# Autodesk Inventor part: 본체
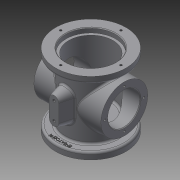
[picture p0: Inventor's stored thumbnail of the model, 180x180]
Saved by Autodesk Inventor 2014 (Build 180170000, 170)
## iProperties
Created: 2018-02
Part Number: 본체
Material: Generic
Document SubType Name: Modeling
Designer: kb542
Density: 1 g/cm^3
Appearance: Default
Author: kb542
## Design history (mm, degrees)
sketch "스케치1"
  geometry: L1 (0, 0)-(0, 108); L2 (-33, 0)-(-52.5, 0); L3 (-52.5, 0)-(-52.5, 10); L4 (-52.5, 10)-(-38, 10); L5 (-38, 10)-(-38, 98); L6 (-38, 98)-(-52.5, 98); L7 (-52.5, 98)-(-52.5, 108); L8 (-52.5, 108)-(-33, 108); L9 (-33, 108)-(-33, 0)
  constraints: 18 end point, 4 parallel, 4 perpendicular, 2 horizontal alignment, 1 vertical
  dimensions: "d0" = 105 diameter of L3 L1; "d1" = 66 diameter of L9 L1; "d2" = 76 diameter of L5 L1; "d3" = 105 diameter of L7 L1; "d4" = 10 distance between parallel lines of L2 L4; "d5" = 10 distance between parallel lines of L6 L8; "d6" = 108 distance between parallel lines of L2 L8
revolve "회전1" sketch "스케치1" stored, may be unused: angle "d7" = 90 deg
node "작업 평면2"
  node "작업 평면1"
sketch "스케치3"
  geometry: L1 (-38, -44)-(-38, 44) reference; L2 (52.5, 44)-(-52.5, 44) reference; C1 r 35 at (0, 0); 3 further points
  constraints: 2 midpoint, 1 centre point, 1 horizontal alignment, 1 vertical alignment
  dimensions: "d10" = 70 diameter of C1
extrude "돌출1" join sketch "스케치3" stored distance "d11" = 10; taper "d12" = 0 deg
sketch "스케치4"
  geometry: C1 r 35 at (0, 0) reference; C2 r 24 at (0, 0); 1 further point
  constraints: 1 centre point, 1 coincident
  dimensions: "d13" = 48 diameter of C2
extrude "돌출2" cut sketch "스케치4" stored distance "d14" = 10; taper "d15" = 0 deg
sketch "스케치5"
  geometry: L1 (108, 33)-(0, 33) reference; L2 (108, -33)-(0, -33) reference; L3 (30, 50)-(30, 33) reference; L4 (30, -33)-(30, -50) reference; L5 (30, 33)-(30, 0); L6 (30, 0)-(0, 0); L7 (0, 0)-(0, 33)
  constraints: 6 end point, 2 perpendicular, 1 collinear, 1 vertical
revolve "회전2" sketch "스케치5" stored, may be unused: angle "d17" = 90 deg
sketch "스케치6"
  geometry: L1 (0, -52.5)-(0, 52.5) reference; L2 (30, 33)-(30, -33) reference; L3 (30, 50)-(30, 33) reference; L4 (30, 33)-(22, 33); L5 (22, 33)-(22, 5); L6 (22, 5)-(16, 5); L7 (16, 5)-(16, 34); L8 (16, 34)-(0, 34); L9 (0, 0)-(30, 0); L10 (108, -33)-(108, 33) reference
  constraints: 12 end point, 3 perpendicular, 2 parallel, 1 midpoint, 1 point on line
  dimensions: "d18" = 16 distance between parallel lines of L1 L7; "d19" = 5 distance between parallel lines of L9 L6; "d20" = 86 distance between parallel lines of L5 L10; "d21" = 68 diameter of L8 L9
revolve "회전3" sketch "스케치6" stored, may be unused: angle "d22" = 90 deg
sketch "스케치7"
  geometry: L1 (108, 33)-(22, 33) reference; L2 (108, -33)-(22, -33) reference; L3 (108, -33)-(108, 33) reference; L4 (108, 0)-(101, 0); L5 (101, 0)-(101, 33); 1 further point
  constraints: 4 end point, 2 perpendicular, 1 midpoint, 1 point on line
  dimensions: "d23" = 7 distance of L4.start L4.end
revolve "회전4" sketch "스케치7" stored, may be unused: angle "d24" = 90 deg
sketch "스케치8"
  geometry: L1 (108, -52.5)-(108, 52.5) reference; L2 (101, -33)-(101, 33) reference; L3 (101, 0)-(108, 0); L4 (101, 37)-(108, 37); L5 (101, 33)-(101, 37); 1 further point
  constraints: 6 end point, 2 midpoint, 2 perpendicular, 2 point on line
  dimensions: "d25" = 74 diameter of L4 L3
revolve "회전5" sketch "스케치8" stored, may be unused: angle "d26" = 90 deg
sketch "스케치9" dims "d27" = 90
  geometry: C1 r 37 at (0, 0) reference; C2 r 52.5 at (0, 0) reference; 2 further points
  constraints: 2 vertical alignment, 1 coincident, 2 other
hole "구멍1" sketch "스케치9" at (0, 45) diameter "d28" = 3.242; stored, may be unused: countersink angle "d32" = 90 deg, drill point angle "d34" = 118 deg; dims "d29" = 4, "d30" = 4, "d31" = 2, "d33" = 6
node "작업 평면3"
sketch "스케치10" dims "d38" = 58
  geometry: C1 r 24 at (0, 0) reference; C2 r 35 at (0, 0) reference; 3 further points
  constraints: 2 vertical alignment, 1 coincident, 2 other
hole "구멍2" sketch "스케치10" at (0, 29) diameter "d39" = 3.242; stored, may be unused: countersink angle "d43" = 90 deg, drill point angle "d45" = 118 deg; dims "d40" = 4, "d41" = 4, "d42" = 2, "d44" = 6
node "작업 평면4"
sketch "스케치12"
  geometry: L1 (67, 0)-(41, 0); L2 (67, 7)-(41, 7); L3 (41, -7)-(67, -7); L4 (19, -50)-(89, -50) reference; A1 r 7 centre (67, 0) between (67, -7) and (67, 7); A2 r 7 centre (41, 0) between (41, 7) and (41, -7); 3 further points
  constraints: 8 end point, 4 point on circle, 4 tangent, 2 centre point, 2 midpoint, 1 horizontal, 1 horizontal alignment, 1 parallel, 1 vertical alignment
  dimensions: "d50" = 7 radius of A1; "d51" = 40 dimension on A2 A1
extrude "돌출3" join sketch "스케치12" stored distance "d52" = 10; taper "d53" = 15 deg
sketch "스케치15"
  geometry: A1 r 7 centre (0, 41) between (-7, 41) and (7, 41) reference; A2 r 7 centre (0, 67) between (7, 67) and (-7, 67) reference; 3 further points
  constraints: 2 coincident
hole "구멍3" sketch "스케치15" at (0, 67), (0, 41) diameter "d54" = 4.134; stored, may be unused: countersink angle "d58" = 90 deg, drill point angle "d60" = 118 deg; dims "d55" = 6, "d56" = 4, "d57" = 2, "d59" = 8
sketch "스케치16"
  geometry: L1 (0, 0)-(43, 0); C1 r 38 at (0, 0) reference; 1 further point
  constraints: 2 end point, 1 coincident, 1 horizontal, 1 other
  dimensions: "d61" = 43 distance of L1.start L1.end
extrude "돌출4" join sketch "스케치16" distance "d62" = 0.5; taper "d63" = 0 deg
chamfer "모따기1" distance "d64" = 1; stored, may be unused: second distance "d65" = 2, angle "d66" = 45 deg
fillet "모깎기1" dims "d67" = 3
fillet "모깎기2" dims "d68" = 3
chamfer "모따기2" distance "d69" = 1; stored, may be unused: second distance "d70" = 2, angle "d71" = 45 deg
fillet "모깎기3" dims "d72" = 3
node "솔리드1"
mirror "대칭1"
pattern_circular "원형 패턴1" dims angle "d36" = 360 deg
pattern_circular "원형 패턴2" dims angle "d47" = 360 deg
mirror "대칭3"
other parameters: "d9" = 12, "d49" = 55
